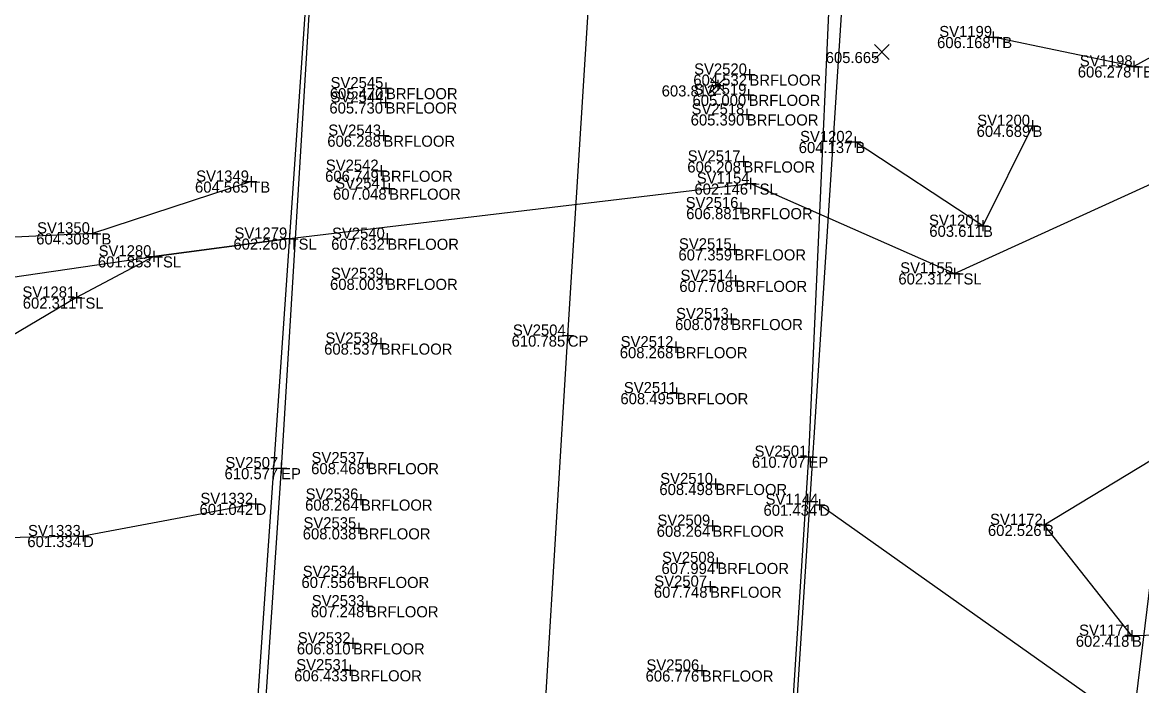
# Model space of a CAD drawing. Extents: x -2 to 1979875, y -2 to 232027.
# Drawn here: x 1978751.3 to 1978801.8, y 231261.4 to 231291.3 of the extents above; entities that cross this region are included whole.
import ezdxf

# ---------------------------------------------------------------- set-up
doc = ezdxf.new("R2010")
doc.units = 0
for name, color, linetype in [('_CIVIL_CONSTRUCTION', 7, 'Continuous'), ('BR_X_SV_Deck_Floor_Text', 7, 'Continuous'), ('BR_X_SV_Deck_Top', 7, 'Continuous'), ('DR_X_Ditch', 7, 'Continuous'), ('GE_P_Alignment', 7, 'Continuous'), ('GE_P_Alignment_1000_Curve_Data', 7, 'Continuous'), ('GE_X_Alignment', 7, 'Continuous'), ('GE_X_Alignment_1000_Curve_Data', 7, 'Continuous'), ('GE_X_Alignment_1000_Stations', 7, 'Continuous'), ('GE_X_Alignment_100_Curve_Data', 7, 'Continuous'), ('GE_X_Alignment_100_Stations', 7, 'Continuous'), ('HY_X_Water_Edge', 7, 'Continuous'), ('SV_X_Random_Point', 7, 'Continuous'), ('SV_X_Toe_of_Slope', 7, 'Continuous'), ('SV_X_Top_of_Bank', 7, 'Continuous')]:
    doc.layers.add(name, color=color, linetype=linetype)

msp = doc.modelspace()

# ---------------------------------------------------------------- linework, layer by layer
at = {"layer": 'BR_X_SV_Deck_Top'}
msp.add_lwpolyline([(1978761.339, 231252.043), (1978764.257, 231294.289), (1978788.348, 231293.277), (1978785.624, 231251.227)], close=True, dxfattribs=at)
at = {"layer": 'DR_X_Ditch'}
for points in [[(1978888.584, 231299.627), (1978879.993, 231287.447), (1978870.172, 231277.213), (1978856.534, 231274.917), (1978839.012, 231271.025), (1978823.007, 231263.425), (1978802.617, 231258.705), (1978787.259, 231269.564)], [(1978761.843, 231269.601), (1978754.066, 231268.151), (1978735.568, 231267.758), (1978719.025, 231269.165), (1978704.244, 231270.76), (1978691.436, 231274.176), (1978676.783, 231277.108), (1978662.935, 231282.94), (1978648.103, 231287.828), (1978629.385, 231288.446)]]:
    msp.add_lwpolyline(points, dxfattribs=at)
at = {"layer": 'GE_P_Alignment'}
for points in [[(1978880.582, 231316.673), (1978878.73, 231308.205), (1978871.111, 231292.475), (1978865.586, 231280.144), (1978848.135, 231280.988), (1978836.093, 231277.946), (1978823.874, 231270.699), (1978811.412, 231263.896), (1978801.351, 231263.66), (1978797.393, 231268.655), (1978813.97, 231278.694), (1978829.592, 231287.989), (1978849.277, 231295.052), (1978867.627, 231302.914), (1978876.642, 231308.974)], [(1978796.872, 231286.639), (1978794.636, 231282.133), (1978788.88, 231285.909)]]:
    msp.add_lwpolyline(points, dxfattribs=at)
at = {"layer": 'GE_P_Alignment_1000_Curve_Data'}
msp.add_lwpolyline([(1978800.253, 231250.204), (1978805.284, 231291.391), (1978804.508, 231297.592), (1978804.78, 231306.073), (1978804.463, 231312.372), (1978805.146, 231324.315), (1978805.161, 231336.373), (1978807.189, 231350.111), (1978807.848, 231360.671), (1978809.086, 231373.348), (1978811.125, 231382.982), (1978814.162, 231421.098), (1978816.965, 231468.048), (1978822.427, 231510.515)], dxfattribs=at)
at = {"layer": 'GE_X_Alignment_1000_Curve_Data'}
msp.add_lwpolyline([(1978774.433, 231252.669), (1978775.92, 231277.185), (1978776.918, 231292.992)], dxfattribs=at)
at = {"layer": 'GE_X_Alignment_1000_Stations'}
for points in [[(1978764.365, 231293.633), (1978762.994, 231271.213), (1978761.795, 231253.289)], [(1978787.697, 231292.411), (1978786.77, 231271.728), (1978785.515, 231252.063)]]:
    msp.add_lwpolyline(points, dxfattribs=at)
at = {"layer": 'GE_X_Alignment_100_Curve_Data'}
for p, q in [((1978794.847, 231290.638), (1978795.347, 231290.638)), ((1978795.097, 231290.888), (1978795.097, 231290.388)), ((1978795.097, 231290.638), (1978795.097, 231290.638)), ((1978801.442, 231289.564), (1978801.442, 231289.064)), ((1978784.106, 231289.197), (1978784.106, 231288.697)), ((1978801.192, 231289.314), (1978801.692, 231289.314)), ((1978801.442, 231289.314), (1978801.442, 231289.314)), ((1978767.718, 231288.586), (1978767.718, 231288.086)), ((1978782.675, 231288.71), (1978782.675, 231288.21)), ((1978783.856, 231288.947), (1978784.356, 231288.947)), ((1978784.106, 231288.947), (1978784.106, 231288.947)), ((1978767.468, 231288.336), (1978767.968, 231288.336)), ((1978767.718, 231288.336), (1978767.718, 231288.336)), ((1978782.425, 231288.46), (1978782.925, 231288.46)), ((1978782.675, 231288.46), (1978782.675, 231288.46)), ((1978783.822, 231288.036), (1978784.322, 231288.036)), ((1978784.072, 231288.286), (1978784.072, 231287.786)), ((1978784.072, 231288.036), (1978784.072, 231288.036)), ((1978767.449, 231287.69), (1978767.949, 231287.69)), ((1978767.699, 231287.94), (1978767.699, 231287.44)), ((1978767.699, 231287.69), (1978767.699, 231287.69)), ((1978783.738, 231287.151), (1978784.238, 231287.151)), ((1978783.988, 231287.401), (1978783.988, 231286.901)), ((1978783.988, 231287.151), (1978783.988, 231287.151)), ((1978796.622, 231286.639), (1978797.122, 231286.639)), ((1978796.872, 231286.889), (1978796.872, 231286.389)), ((1978796.872, 231286.639), (1978796.872, 231286.639)), ((1978767.355, 231286.194), (1978767.855, 231286.194)), ((1978767.605, 231286.444), (1978767.605, 231285.944)), ((1978767.605, 231286.194), (1978767.605, 231286.194)), ((1978788.88, 231286.159), (1978788.88, 231285.659)), ((1978788.63, 231285.909), (1978789.13, 231285.909)), ((1978788.88, 231285.909), (1978788.88, 231285.909)), ((1978783.587, 231285.032), (1978784.087, 231285.032)), ((1978783.837, 231285.282), (1978783.837, 231284.782)), ((1978783.837, 231285.032), (1978783.837, 231285.032)), ((1978767.248, 231284.615), (1978767.748, 231284.615)), ((1978767.498, 231284.865), (1978767.498, 231284.365)), ((1978767.498, 231284.615), (1978767.498, 231284.615)), ((1978761.395, 231284.125), (1978761.895, 231284.125)), ((1978761.645, 231284.375), (1978761.645, 231283.875)), ((1978761.645, 231284.125), (1978761.645, 231284.125)), ((1978767.863, 231284.057), (1978767.863, 231283.557)), ((1978783.909, 231284.036), (1978784.409, 231284.036)), ((1978784.159, 231284.286), (1978784.159, 231283.786)), ((1978784.159, 231284.036), (1978784.159, 231284.036)), ((1978767.613, 231283.807), (1978768.113, 231283.807)), ((1978767.863, 231283.807), (1978767.863, 231283.807)), ((1978783.726, 231283.18), (1978783.726, 231282.68)), ((1978783.476, 231282.93), (1978783.976, 231282.93)), ((1978783.726, 231282.93), (1978783.726, 231282.93)), ((1978754.482, 231282.041), (1978754.482, 231281.541)), ((1978794.386, 231282.133), (1978794.886, 231282.133)), ((1978794.636, 231282.383), (1978794.636, 231281.883)), ((1978794.636, 231282.133), (1978794.636, 231282.133)), ((1978754.232, 231281.791), (1978754.732, 231281.791)), ((1978754.482, 231281.791), (1978754.482, 231281.791)), ((1978763.121, 231281.556), (1978763.621, 231281.556)), ((1978763.371, 231281.806), (1978763.371, 231281.306)), ((1978763.371, 231281.556), (1978763.371, 231281.556)), ((1978767.529, 231281.55), (1978768.029, 231281.55)), ((1978767.779, 231281.8), (1978767.779, 231281.3)), ((1978767.779, 231281.55), (1978767.779, 231281.55)), ((1978757.257, 231281.005), (1978757.257, 231280.505)), ((1978783.177, 231281.071), (1978783.677, 231281.071)), ((1978783.427, 231281.321), (1978783.427, 231280.821)), ((1978783.427, 231281.071), (1978783.427, 231281.071)), ((1978757.007, 231280.755), (1978757.507, 231280.755)), ((1978757.257, 231280.755), (1978757.257, 231280.755)), ((1978767.722, 231279.993), (1978767.722, 231279.493)), ((1978793.101, 231279.988), (1978793.601, 231279.988)), ((1978793.351, 231280.238), (1978793.351, 231279.738)), ((1978793.351, 231279.988), (1978793.351, 231279.988)), ((1978767.472, 231279.743), (1978767.972, 231279.743)), ((1978767.722, 231279.743), (1978767.722, 231279.743)), ((1978783.227, 231279.651), (1978783.727, 231279.651)), ((1978783.477, 231279.901), (1978783.477, 231279.401)), ((1978783.477, 231279.651), (1978783.477, 231279.651)), ((1978753.761, 231279.148), (1978753.761, 231278.648)), ((1978753.511, 231278.898), (1978754.011, 231278.898)), ((1978753.761, 231278.898), (1978753.761, 231278.898)), ((1978783.285, 231278.182), (1978783.285, 231277.682)), ((1978775.92, 231277.435), (1978775.92, 231276.935)), ((1978783.035, 231277.932), (1978783.535, 231277.932)), ((1978783.285, 231277.932), (1978783.285, 231277.932)), ((1978767.483, 231277.076), (1978767.483, 231276.576)), ((1978775.67, 231277.185), (1978776.17, 231277.185)), ((1978775.92, 231277.185), (1978775.92, 231277.185)), ((1978767.233, 231276.826), (1978767.733, 231276.826)), ((1978767.483, 231276.826), (1978767.483, 231276.826)), ((1978780.541, 231276.663), (1978781.041, 231276.663)), ((1978780.791, 231276.913), (1978780.791, 231276.413)), ((1978780.791, 231276.663), (1978780.791, 231276.663)), ((1978780.575, 231274.591), (1978781.075, 231274.591)), ((1978780.825, 231274.841), (1978780.825, 231274.341)), ((1978780.825, 231274.591), (1978780.825, 231274.591)), ((1978786.77, 231271.978), (1978786.77, 231271.478)), ((1978762.994, 231271.463), (1978762.994, 231270.963)), ((1978766.627, 231271.438), (1978767.127, 231271.438)), ((1978766.877, 231271.688), (1978766.877, 231271.188)), ((1978766.877, 231271.438), (1978766.877, 231271.438)), ((1978786.52, 231271.728), (1978787.02, 231271.728)), ((1978786.77, 231271.728), (1978786.77, 231271.728)), ((1978762.744, 231271.213), (1978763.244, 231271.213)), ((1978762.994, 231271.213), (1978762.994, 231271.213)), ((1978782.327, 231270.498), (1978782.827, 231270.498)), ((1978782.577, 231270.748), (1978782.577, 231270.248)), ((1978782.577, 231270.498), (1978782.577, 231270.498)), ((1978766.59, 231270.046), (1978766.59, 231269.546)), ((1978761.593, 231269.601), (1978762.093, 231269.601)), ((1978761.843, 231269.851), (1978761.843, 231269.351)), ((1978761.843, 231269.601), (1978761.843, 231269.601)), ((1978766.34, 231269.796), (1978766.84, 231269.796)), ((1978766.59, 231269.796), (1978766.59, 231269.796)), ((1978787.009, 231269.564), (1978787.509, 231269.564)), ((1978787.259, 231269.814), (1978787.259, 231269.314)), ((1978787.259, 231269.564), (1978787.259, 231269.564)), ((1978782.442, 231268.868), (1978782.442, 231268.368)), ((1978797.393, 231268.905), (1978797.393, 231268.405)), ((1978754.066, 231268.401), (1978754.066, 231267.901)), ((1978766.247, 231268.5), (1978766.747, 231268.5)), ((1978766.497, 231268.75), (1978766.497, 231268.25)), ((1978766.497, 231268.5), (1978766.497, 231268.5)), ((1978782.192, 231268.618), (1978782.692, 231268.618)), ((1978782.442, 231268.618), (1978782.442, 231268.618)), ((1978797.143, 231268.655), (1978797.643, 231268.655)), ((1978797.393, 231268.655), (1978797.393, 231268.655)), ((1978753.816, 231268.151), (1978754.316, 231268.151)), ((1978754.066, 231268.151), (1978754.066, 231268.151)), ((1978782.409, 231266.94), (1978782.909, 231266.94)), ((1978782.659, 231267.19), (1978782.659, 231266.69)), ((1978782.659, 231266.94), (1978782.659, 231266.94)), ((1978766.442, 231266.56), (1978766.442, 231266.06)), ((1978766.192, 231266.31), (1978766.692, 231266.31)), ((1978766.442, 231266.31), (1978766.442, 231266.31)), ((1978782.08, 231265.871), (1978782.58, 231265.871)), ((1978782.33, 231266.121), (1978782.33, 231265.621)), ((1978782.33, 231265.871), (1978782.33, 231265.871)), ((1978766.608, 231264.989), (1978767.108, 231264.989)), ((1978766.858, 231265.239), (1978766.858, 231264.739)), ((1978766.858, 231264.989), (1978766.858, 231264.989)), ((1978801.351, 231263.91), (1978801.351, 231263.41)), ((1978765.983, 231263.318), (1978766.483, 231263.318)), ((1978766.233, 231263.568), (1978766.233, 231263.068)), ((1978766.233, 231263.318), (1978766.233, 231263.318)), ((1978801.101, 231263.66), (1978801.601, 231263.66)), ((1978801.351, 231263.66), (1978801.351, 231263.66)), ((1978766.106, 231262.354), (1978766.106, 231261.854)), ((1978781.958, 231262.343), (1978781.958, 231261.843)), ((1978765.856, 231262.104), (1978766.356, 231262.104)), ((1978766.106, 231262.104), (1978766.106, 231262.104)), ((1978781.708, 231262.093), (1978782.208, 231262.093)), ((1978781.958, 231262.093), (1978781.958, 231262.093))]:
    msp.add_line(p, q, dxfattribs=at)
at = {"layer": 'HY_X_Water_Edge'}
msp.add_lwpolyline([(1978738.528, 231278.008), (1978757.257, 231280.755), (1978763.371, 231281.556), (1978784.159, 231284.036), (1978793.351, 231279.988), (1978807.698, 231286.514), (1978821.562, 231291.295), (1978840.747, 231297.53), (1978857.609, 231304.298), (1978872.974, 231309.553), (1978877.125, 231314.237), (1978883.495, 231319.371), (1978882.175, 231341.325), (1978883.048, 231360.363), (1978875.551, 231375.847), (1978868.903, 231394.228), (1978864.235, 231416.891), (1978862.047, 231444.318), (1978861.234, 231465.995)], dxfattribs=at)
at = {"layer": 'SV_X_Random_Point'}
for p, q in [((1978789.748, 231289.63), (1978790.414, 231290.298)), ((1978789.748, 231290.298), (1978790.414, 231289.63)), ((1978782.342, 231288.126), (1978783.008, 231288.794)), ((1978782.342, 231288.794), (1978783.008, 231288.126))]:
    msp.add_line(p, q, dxfattribs=at)
at = {"layer": 'SV_X_Toe_of_Slope'}
for points in [[(1978784.159, 231284.036), (1978793.351, 231279.988), (1978807.698, 231286.514), (1978821.562, 231291.295), (1978840.747, 231297.53), (1978857.609, 231304.298), (1978872.974, 231309.553), (1978877.125, 231314.237), (1978878.34, 231321.237)], [(1978763.371, 231281.556), (1978757.257, 231280.755), (1978753.761, 231278.898), (1978748.177, 231275.596), (1978738.528, 231278.008), (1978722.197, 231278.71), (1978711.084, 231279.554), (1978693.826, 231282.342), (1978680.005, 231283.016), (1978670.013, 231286.083), (1978658.457, 231291.257), (1978640.318, 231295.767), (1978627.995, 231296.512)]]:
    msp.add_lwpolyline(points, dxfattribs=at)
at = {"layer": 'SV_X_Top_of_Bank'}
for points in [[(1978874.834, 231321.265), (1978869.013, 231312.553), (1978850.46, 231306.223), (1978834.564, 231301.781), (1978822.93, 231297.571), (1978810.304, 231294.189), (1978801.442, 231289.314), (1978795.097, 231290.638)], [(1978761.645, 231284.125), (1978754.482, 231281.791), (1978739.179, 231281.066)]]:
    msp.add_lwpolyline(points, dxfattribs=at)

# ---------------------------------------------------------------- texts
at = {"layer": '_CIVIL_CONSTRUCTION'}
for s, p in [('606.168', (1978792.567, 231290.138)), ('605.665', (1978787.546, 231289.464)), ('606.278', (1978798.912, 231288.814)), ('603.813', (1978780.15, 231287.96)), ('604.689', (1978794.351, 231286.139)), ('604.137', (1978786.329, 231285.409)), ('604.565', (1978759.11, 231283.625)), ('602.146', (1978781.627, 231283.536)), ('603.611', (1978792.218, 231281.633)), ('604.308', (1978751.952, 231281.291)), ('602.260', (1978760.841, 231281.056)), ('601.853', (1978754.732, 231280.255)), ('602.312', (1978790.823, 231279.488)), ('602.311', (1978751.343, 231278.398)), ('610.785', (1978773.385, 231276.685)), ('610.707', (1978784.219, 231271.228)), ('610.577', (1978760.443, 231270.713)), ('601.042', (1978759.315, 231269.101)), ('601.434', (1978784.743, 231269.064)), ('602.526', (1978794.861, 231268.155)), ('601.334', (1978751.55, 231267.651)), ('602.418', (1978798.821, 231263.16))]:
    msp.add_text(s, height=0.5, dxfattribs=at).set_placement(p)
at = {"layer": 'BR_X_SV_Deck_Floor_Text'}
for s, p in [('SV2520', (1978781.614, 231288.947)), ('SV2545', (1978765.221, 231288.336)), ('604.532', (1978781.578, 231288.447)), ('SV2519', (1978781.59, 231288.036)), ('BRFLOOR', (1978784.106, 231288.447)), ('605.470', (1978765.188, 231287.836)), ('SV2544', (1978765.222, 231287.69)), ('BRFLOOR', (1978767.718, 231287.836)), ('605.000', (1978781.542, 231287.536)), ('BRFLOOR', (1978784.072, 231287.536)), ('605.730', (1978765.169, 231287.19)), ('BRFLOOR', (1978767.699, 231287.19)), ('SV2518', (1978781.497, 231287.151)), ('605.390', (1978781.458, 231286.651)), ('BRFLOOR', (1978783.988, 231286.651)), ('SV2543', (1978765.119, 231286.194)), ('606.288', (1978765.075, 231285.694)), ('BRFLOOR', (1978767.605, 231285.694)), ('SV2517', (1978781.324, 231285.032)), ('SV2542', (1978765.008, 231284.615)), ('606.208', (1978781.307, 231284.532)), ('BRFLOOR', (1978783.837, 231284.532)), ('606.749', (1978764.977, 231284.115)), ('BRFLOOR', (1978767.498, 231284.115)), ('SV2541', (1978765.431, 231283.807)), ('607.048', (1978765.333, 231283.307)), ('BRFLOOR', (1978767.863, 231283.307)), ('SV2516', (1978781.232, 231282.93)), ('606.881', (1978781.256, 231282.43)), ('BRFLOOR', (1978783.726, 231282.43)), ('SV2540', (1978765.287, 231281.55)), ('607.632', (1978765.251, 231281.05)), ('BRFLOOR', (1978767.779, 231281.05)), ('SV2515', (1978780.93, 231281.071)), ('607.359', (1978780.906, 231280.571)), ('BRFLOOR', (1978783.427, 231280.571)), ('SV2539', (1978765.24, 231279.743)), ('SV2514', (1978781, 231279.651)), ('608.003', (1978765.197, 231279.243)), ('BRFLOOR', (1978767.722, 231279.243)), ('607.708', (1978780.947, 231279.151)), ('BRFLOOR', (1978783.477, 231279.151)), ('608.078', (1978780.755, 231277.432)), ('SV2513', (1978780.799, 231277.932)), ('BRFLOOR', (1978783.285, 231277.432)), ('SV2538', (1978764.992, 231276.826)), ('SV2512', (1978778.301, 231276.663)), ('608.537', (1978764.932, 231276.326)), ('BRFLOOR', (1978767.483, 231276.326)), ('608.268', (1978778.261, 231276.163)), ('BRFLOOR', (1978780.791, 231276.163)), ('SV2511', (1978778.445, 231274.591)), ('608.495', (1978778.29, 231274.091)), ('BRFLOOR', (1978780.825, 231274.091)), ('SV2537', (1978764.364, 231271.438)), ('608.468', (1978764.347, 231270.938)), ('BRFLOOR', (1978766.877, 231270.938)), ('SV2510', (1978780.085, 231270.498)), ('608.498', (1978780.047, 231269.998)), ('BRFLOOR', (1978782.577, 231269.998)), ('SV2536', (1978764.096, 231269.796)), ('608.264', (1978764.074, 231269.296)), ('BRFLOOR', (1978766.59, 231269.296)), ('SV2535', (1978764, 231268.5)), ('SV2509', (1978779.96, 231268.618)), ('608.038', (1978763.967, 231268)), ('BRFLOOR', (1978766.497, 231268)), ('608.264', (1978779.926, 231268.118)), ('BRFLOOR', (1978782.442, 231268.118)), ('SV2508', (1978780.168, 231266.94)), ('607.994', (1978780.143, 231266.44)), ('BRFLOOR', (1978782.659, 231266.44)), ('SV2534', (1978763.965, 231266.31)), ('SV2507', (1978779.817, 231265.871)), ('607.556', (1978763.91, 231265.81)), ('BRFLOOR', (1978766.442, 231265.81)), ('607.748', (1978779.8, 231265.371)), ('BRFLOOR', (1978782.33, 231265.371)), ('SV2533', (1978764.372, 231264.989)), ('607.248', (1978764.328, 231264.489)), ('BRFLOOR', (1978766.858, 231264.489)), ('SV2532', (1978763.743, 231263.318)), ('606.810', (1978763.703, 231262.818)), ('BRFLOOR', (1978766.233, 231262.818)), ('SV2531', (1978763.674, 231262.104)), ('SV2506', (1978779.464, 231262.093)), ('606.433', (1978763.581, 231261.604)), ('BRFLOOR', (1978766.106, 231261.604)), ('606.776', (1978779.426, 231261.593)), ('BRFLOOR', (1978781.958, 231261.593))]:
    msp.add_text(s, height=0.5, dxfattribs=at).set_placement(p)
at = {"layer": 'GE_X_Alignment'}
for s, p in [('SV1199', (1978792.667, 231290.638)), ('SV1198', (1978799.003, 231289.314)), ('SV1200', (1978794.38, 231286.639)), ('SV1202', (1978786.39, 231285.909)), ('SV1349', (1978759.163, 231284.125)), ('SV1154', (1978781.734, 231284.036)), ('SV1201', (1978792.204, 231282.133)), ('SV1350', (1978751.99, 231281.791)), ('SV1279', (1978760.889, 231281.556)), ('SV1280', (1978754.765, 231280.755)), ('SV1155', (1978790.906, 231279.988)), ('SV1281', (1978751.329, 231278.898)), ('SV2504', (1978773.443, 231277.185)), ('SV2501', (1978784.338, 231271.728)), ('SV2507', (1978760.481, 231271.213)), ('SV1332', (1978759.353, 231269.601)), ('SV1144', (1978784.834, 231269.564)), ('SV1172', (1978794.955, 231268.655)), ('SV1333', (1978751.58, 231268.151)), ('SV1171', (1978798.971, 231263.66))]:
    msp.add_text(s, height=0.5, dxfattribs=at).set_placement(p)
at = {"layer": 'GE_X_Alignment_100_Stations'}
for s, p in [('TB', (1978795.097, 231290.138)), ('TB', (1978801.442, 231288.814)), ('B', (1978796.872, 231286.139)), ('B', (1978788.88, 231285.409)), ('TB', (1978761.645, 231283.625)), ('TSL', (1978784.159, 231283.536)), ('B', (1978794.636, 231281.633)), ('TB', (1978754.482, 231281.291)), ('TSL', (1978763.371, 231281.056)), ('TSL', (1978757.257, 231280.255)), ('TSL', (1978793.351, 231279.488)), ('TSL', (1978753.761, 231278.398)), ('CP', (1978775.92, 231276.685)), ('EP', (1978786.77, 231271.228)), ('EP', (1978762.994, 231270.713)), ('D', (1978761.843, 231269.101)), ('D', (1978787.259, 231269.064)), ('B', (1978797.393, 231268.155)), ('D', (1978754.066, 231267.651)), ('B', (1978801.351, 231263.16))]:
    msp.add_text(s, height=0.5, dxfattribs=at).set_placement(p)

doc.saveas('drawing.dxf')
